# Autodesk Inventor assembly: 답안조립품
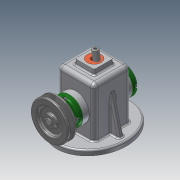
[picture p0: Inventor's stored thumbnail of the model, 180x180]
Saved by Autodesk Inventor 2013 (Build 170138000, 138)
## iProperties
Created: 2017-07
Part Number: 답안조립품
Document SubType Name: Assembly
Designer: Administrator
Author: Administrator
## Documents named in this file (16)
- C:\Users\Administrator\Desktop\470708V1023\답안조립품.iam
- C:\Users\Administrator\Desktop\470708V1023\본체.ipt
- C:\Users\Administrator\Desktop\470708V1023\편심축.ipt
- C:\Users\Administrator\Desktop\470708V1023\베어링 12 x 32 x 10.ipt
- C:\Users\Administrator\Desktop\470708V1023\링크.ipt
- C:\Users\Administrator\Desktop\470708V1023\부시.ipt
- C:\Users\Administrator\Desktop\470708V1023\뒤커버.ipt
- C:\Users\Administrator\Desktop\470708V1023\앞커버.ipt
- C:\Users\Administrator\Desktop\470708V1023\슬라이드.ipt
- C:\Users\Administrator\Desktop\470708V1023\고정핀 1.2 x  8.ipt
- C:\Users\Administrator\Desktop\470708V1023\핀 5 x 18.ipt
- C:\Users\Administrator\Desktop\470708V1023\오일실 12 25 7.ipt
- C:\Users\Administrator\Desktop\470708V1023\볼트 M4 x 12.ipt
- C:\Users\Administrator\Desktop\470708V1023\V벨트풀리.ipt
- C:\Users\Administrator\Desktop\470708V1023\키 4 x 4 x 10.ipt
- C:\Users\Administrator\Desktop\470708V1023\멈춤나사 M3x8.ipt
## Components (3 placed, 3 different names)
1. 고정핀 1.2 x  8:1
2. 핀 5 x 18:1
3. V벨트풀리:1
